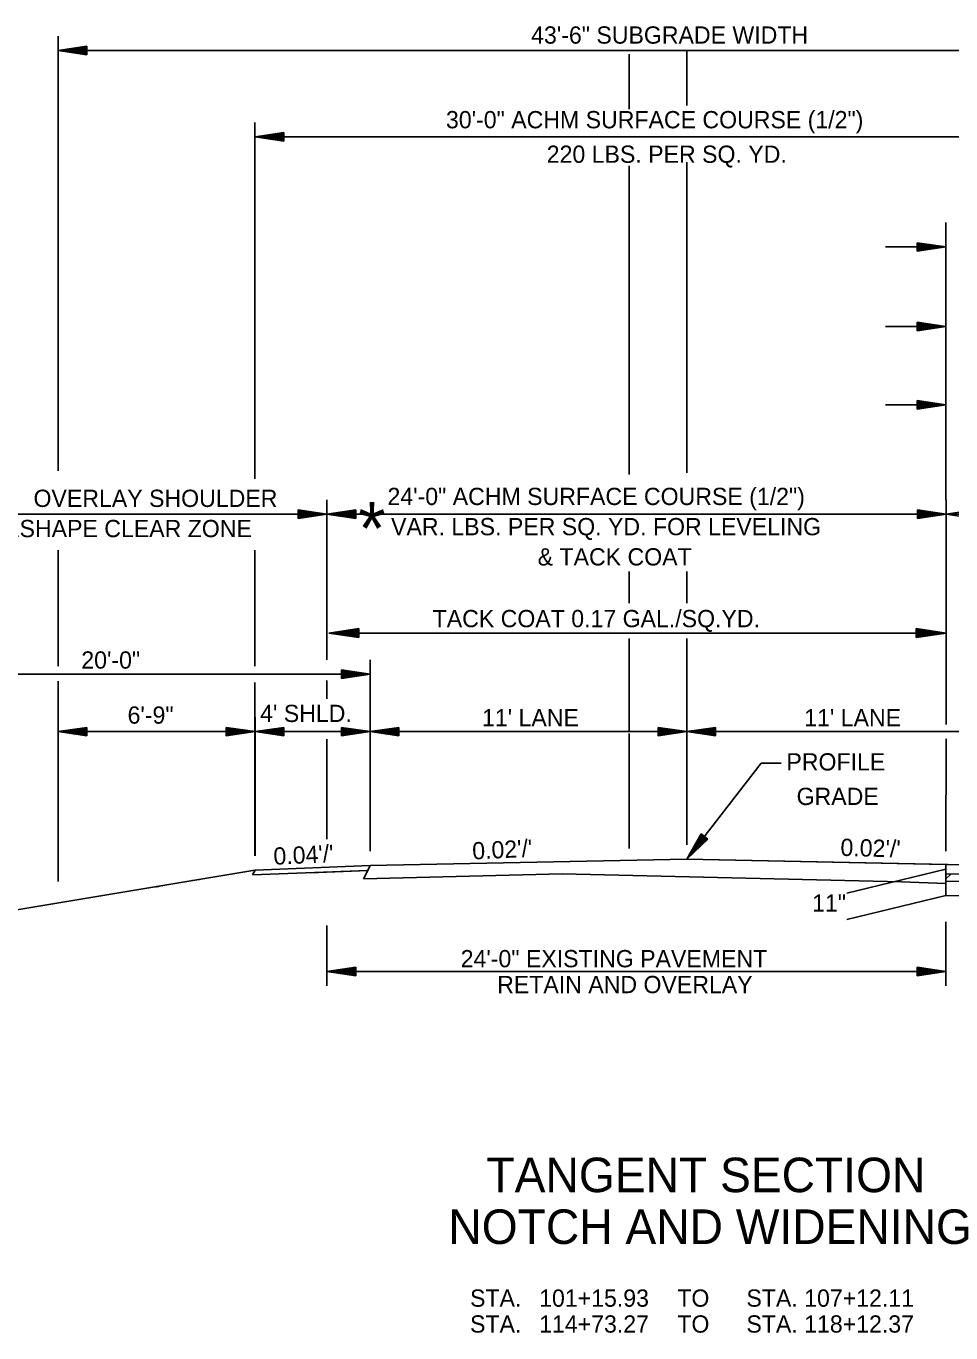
# Model space of a CAD drawing. Extents: x -900 to 15312, y 1857 to 2945.
# Drawn here: x 1911.7 to 2232.9, y 1982.2 to 2436.5 of the extents above; entities that cross this region are included whole.
import ezdxf

# ---------------------------------------------------------------- set-up
doc = ezdxf.new("R2010")
doc.units = 0
for name, color, linetype in [('Default', 7, 'Continuous'), ('R_Annotation', 7, 'Continuous'), ('R_Centerline', 7, 'Continuous'), ('R_Dimension', 7, 'Continuous')]:
    doc.layers.add(name, color=color, linetype=linetype)

msp = doc.modelspace()

# ---------------------------------------------------------------- linework, layer by layer
at = {"layer": 'Default'}
for p, q in [((2141.18, 2146.88), (2031.18, 2144.68)), ((2231.18, 2145.08), (2141.18, 2146.88)), ((2251.18, 2144.68), (2231.18, 2145.08)), ((2231.18, 2145.08), (2231.18, 2141.74)), ((2028.88, 2140.09), (2097.89, 2141.76)), ((2231.18, 2141.74), (2252.86, 2141.31)), ((2231.18, 2140.04), (2232.85, 2141.71))]:
    msp.add_line(p, q, dxfattribs=at)
for points in [[(2031.18, 2144.68), (2030.33, 2142.98), (2028.88, 2140.09)], [(2231.18, 2138.4), (2231.18, 2139.24), (2231.18, 2141.74), (2231.18, 2145.08)], [(2097.89, 2141.76), (2146.95, 2140.6), (2215.71, 2138.96), (2231.18, 2138.4)]]:
    msp.add_lwpolyline(points, dxfattribs=at)
at = {"layer": 'R_Annotation'}
for p, q in [((1991.18, 2143.08), (2031.18, 2144.68)), ((2031.18, 2144.68), (2141.18, 2146.88)), ((2251.18, 2144.68), (2141.18, 2146.88)), ((2231.18, 2145.08), (2231.18, 2134.24)), ((1991.17, 2143.08), (1831.17, 2116.41)), ((1991.18, 2143.08), (1990.33, 2141.38)), ((2010.33, 2142.18), (2030.33, 2142.98)), ((2252.86, 2141.31), (2231.18, 2141.74)), ((2254.13, 2138.78), (2231.18, 2139.24)), ((2359.6, 2131.67), (2231.18, 2134.24))]:
    msp.add_line(p, q, dxfattribs=at)
for points in [[(1971.66, 2139.82), (1971.74, 2139.83), (1971.82, 2139.82), (1971.9, 2139.82)], [(1977.02, 2140.72), (1977.02, 2140.72), (1977.02, 2140.72), (1977.02, 2140.72)], [(1977.08, 2140.72), (1977.08, 2140.72), (1977.08, 2140.72), (1977.08, 2140.73)], [(1982.92, 2141.7), (1982.87, 2141.69), (1982.82, 2141.68), (1982.77, 2141.68)], [(1984.69, 2142), (1984.69, 2142), (1984.69, 2142), (1984.7, 2142)], [(1984.7, 2142), (1984.72, 2142), (1984.74, 2142), (1984.76, 2142)], [(1957.97, 2137.54), (1957.93, 2137.53), (1957.6, 2137.42), (1957.27, 2137.34), (1956.85, 2137.31), (1956.72, 2137.31), (1956.59, 2137.31)], [(1959.1, 2137.66), (1959.12, 2137.66), (1959.14, 2137.66), (1959.16, 2137.66)], [(1969.34, 2139.42), (1969.31, 2139.42), (1969.27, 2139.42), (1969.23, 2139.42), (1969.21, 2139.42)]]:
    msp.add_open_spline(points, degree=3, dxfattribs=at)
at = {"layer": 'R_Centerline'}
for p, q in [((2121.18, 2407.57), (2121.18, 2426.69)), ((2141.18, 2408.83), (2141.18, 2427.95)), ((2121.18, 2280.6), (2121.18, 2387.88)), ((2141.18, 2281.2), (2141.18, 2389.14)), ((2121.18, 2235.82), (2121.18, 2246.84)), ((2141.18, 2235.82), (2141.18, 2246.84)), ((2121.18, 2191.65), (2121.18, 2223.59)), ((2141.18, 2151.88), (2141.18, 2223.59)), ((2121.18, 2150.62), (2121.18, 2190.61))]:
    msp.add_line(p, q, dxfattribs=at)
at = {"layer": 'R_Dimension'}
for p, q in [((1922.75, 2281.86), (1922.75, 2432.95)), ((1932.75, 2429.45), (1922.75, 2427.95)), ((1922.75, 2427.95), (2359.6, 2427.95)), ((1932.75, 2426.45), (1922.75, 2427.95)), ((1932.75, 2429.2), (1924.42, 2427.95)), ((1932.75, 2426.7), (1924.42, 2427.95)), ((1932.75, 2428.94), (1926.14, 2427.95)), ((1932.75, 2426.95), (1926.14, 2427.95)), ((1932.75, 2428.69), (1927.81, 2427.95)), ((1932.75, 2427.2), (1927.81, 2427.95)), ((1932.75, 2428.43), (1929.5, 2427.95)), ((1932.75, 2427.46), (1929.5, 2427.95)), ((1932.75, 2428.18), (1931.17, 2427.95)), ((1932.75, 2427.71), (1931.17, 2427.95)), ((1932.75, 2429.45), (1932.75, 2426.45)), ((1991.17, 2279.1), (1991.17, 2402.95)), ((2001.18, 2399.45), (1991.18, 2397.95)), ((2001.18, 2399.2), (1992.85, 2397.95)), ((2001.18, 2398.94), (1994.57, 2397.95)), ((2001.18, 2398.69), (1996.23, 2397.95)), ((2001.18, 2398.44), (1997.93, 2397.95)), ((2001.18, 2396.45), (2001.18, 2399.45)), ((2291.18, 2397.95), (1991.17, 2397.95)), ((2001.18, 2396.45), (1991.18, 2397.95)), ((2001.18, 2396.7), (1992.85, 2397.95)), ((2001.18, 2396.95), (1994.57, 2397.95)), ((2001.18, 2397.2), (1996.23, 2397.95)), ((2001.18, 2397.46), (1997.93, 2397.95)), ((2001.18, 2398.18), (1999.6, 2397.95)), ((2001.18, 2397.71), (1999.6, 2397.95)), ((2231.18, 2359.69), (2231.18, 2368.23)), ((2210.19, 2359.69), (2231.07, 2359.69)), ((2221.18, 2361.19), (2231.18, 2359.69)), ((2221.18, 2358.19), (2221.18, 2361.19)), ((2221.18, 2360.94), (2229.51, 2359.69)), ((2221.18, 2360.68), (2227.79, 2359.69)), ((2221.18, 2360.43), (2226.12, 2359.69)), ((2221.18, 2360.18), (2224.43, 2359.69)), ((2221.18, 2359.92), (2222.76, 2359.69)), ((2221.18, 2358.19), (2231.18, 2359.69)), ((2221.18, 2359.2), (2224.43, 2359.69)), ((2221.18, 2358.69), (2227.79, 2359.69)), ((2221.18, 2358.44), (2229.51, 2359.69)), ((2221.18, 2358.94), (2226.12, 2359.69)), ((2221.18, 2359.45), (2222.76, 2359.69)), ((2231.18, 2304.87), (2231.18, 2359.69)), ((2210.19, 2332.02), (2231.18, 2332.02)), ((2221.18, 2333.52), (2231.18, 2332.02)), ((2221.18, 2330.52), (2221.18, 2333.52)), ((2221.18, 2333.27), (2229.51, 2332.02)), ((2221.18, 2333.02), (2227.79, 2332.02)), ((2221.18, 2332.77), (2226.12, 2332.02)), ((2221.18, 2332.51), (2224.43, 2332.02)), ((2221.18, 2332.26), (2222.76, 2332.02)), ((2221.18, 2330.52), (2231.18, 2332.02)), ((2221.18, 2331.54), (2224.43, 2332.02)), ((2221.18, 2331.03), (2227.79, 2332.02)), ((2221.18, 2330.77), (2229.51, 2332.02)), ((2221.18, 2331.28), (2226.12, 2332.02)), ((2221.18, 2331.79), (2222.76, 2332.02)), ((2210.19, 2304.87), (2231.18, 2304.87)), ((2221.18, 2306.37), (2231.18, 2304.87)), ((2221.18, 2303.37), (2221.18, 2306.37)), ((2221.18, 2306.12), (2229.51, 2304.87)), ((2221.18, 2305.86), (2227.79, 2304.87)), ((2221.18, 2305.61), (2226.12, 2304.87)), ((2221.18, 2305.36), (2224.43, 2304.87)), ((2221.18, 2305.1), (2222.76, 2304.87)), ((2221.18, 2303.37), (2231.18, 2304.87)), ((2221.18, 2304.38), (2224.43, 2304.87)), ((2221.18, 2303.87), (2227.79, 2304.87)), ((2221.18, 2303.62), (2229.51, 2304.87)), ((2221.18, 2304.12), (2226.12, 2304.87)), ((2221.18, 2304.63), (2222.76, 2304.87)), ((2231.18, 2271.81), (2231.18, 2304.87)), ((2016.18, 2216.21), (2016.18, 2271.81)), ((2231.2, 2193.71), (2231.25, 2271.81)), ((1868.55, 2266.81), (2309.56, 2266.81)), ((2006.18, 2268.31), (2016.18, 2266.81)), ((2006.18, 2265.31), (2006.18, 2268.31)), ((2006.18, 2268.06), (2014.51, 2266.81)), ((2006.18, 2267.8), (2012.79, 2266.81)), ((2006.18, 2267.55), (2011.12, 2266.81)), ((2006.18, 2267.3), (2009.43, 2266.81)), ((2006.18, 2267.04), (2007.76, 2266.81)), ((2006.18, 2265.31), (2016.18, 2266.81)), ((2006.18, 2266.32), (2009.43, 2266.81)), ((2006.18, 2265.81), (2012.79, 2266.81)), ((2006.18, 2265.56), (2014.51, 2266.81)), ((2006.18, 2266.06), (2011.12, 2266.81)), ((2006.18, 2266.57), (2007.76, 2266.81)), ((2026.18, 2268.31), (2016.18, 2266.81)), ((2026.18, 2265.31), (2016.18, 2266.81)), ((2026.18, 2268.06), (2017.85, 2266.81)), ((2026.18, 2265.56), (2017.85, 2266.81)), ((2026.18, 2267.8), (2019.57, 2266.81)), ((2026.18, 2265.81), (2019.57, 2266.81)), ((2026.18, 2267.55), (2021.23, 2266.81)), ((2026.18, 2266.06), (2021.23, 2266.81)), ((2026.18, 2267.3), (2022.93, 2266.81)), ((2026.18, 2266.32), (2022.93, 2266.81)), ((2026.18, 2267.04), (2024.6, 2266.81)), ((2026.18, 2266.57), (2024.6, 2266.81)), ((2026.18, 2265.31), (2026.18, 2268.31)), ((2221.25, 2268.31), (2231.25, 2266.81)), ((2221.25, 2268.31), (2221.25, 2265.31)), ((2221.25, 2268.06), (2229.58, 2266.81)), ((2221.25, 2267.8), (2227.86, 2266.81)), ((2221.25, 2267.55), (2226.19, 2266.81)), ((2221.25, 2267.29), (2224.5, 2266.81)), ((2221.25, 2267.04), (2222.83, 2266.81)), ((2221.25, 2265.31), (2231.25, 2266.81)), ((2221.25, 2266.32), (2224.5, 2266.81)), ((2221.25, 2265.81), (2227.86, 2266.81)), ((2221.25, 2265.56), (2229.58, 2266.81)), ((2221.25, 2266.06), (2226.19, 2266.81)), ((2221.25, 2266.57), (2222.83, 2266.81)), ((2241.25, 2268.31), (2231.25, 2266.81)), ((2241.25, 2265.31), (2231.25, 2266.81)), ((1922.75, 2213.97), (1922.75, 2254.31)), ((1991.17, 2213.97), (1991.17, 2254.31)), ((2027.23, 2227.06), (2016.82, 2225.5)), ((2027.23, 2226.8), (2018.56, 2225.5)), ((2027.23, 2226.53), (2020.35, 2225.5)), ((2027.23, 2226.27), (2022.07, 2225.5)), ((2027.23, 2226.01), (2023.84, 2225.5)), ((2027.23, 2223.94), (2027.23, 2227.06)), ((2220.81, 2227.06), (2231.22, 2225.5)), ((2220.81, 2227.06), (2220.81, 2223.94)), ((2220.81, 2226.8), (2229.48, 2225.5)), ((2220.81, 2226.53), (2227.69, 2225.5)), ((2220.81, 2226.27), (2225.97, 2225.5)), ((2220.81, 2226), (2224.2, 2225.5)), ((2027.23, 2223.94), (2016.82, 2225.5)), ((2231.22, 2225.5), (2016.82, 2225.5)), ((2027.23, 2224.2), (2018.56, 2225.5)), ((2027.23, 2224.47), (2020.35, 2225.5)), ((2027.23, 2224.73), (2022.07, 2225.5)), ((2027.23, 2225), (2023.84, 2225.5)), ((2027.23, 2225.74), (2025.58, 2225.5)), ((2027.23, 2225.26), (2025.58, 2225.5)), ((2056.82, 2225.5), (2055.56, 2225.5)), ((2220.81, 2225.74), (2222.46, 2225.5)), ((2220.81, 2223.94), (2231.22, 2225.5)), ((2220.81, 2224.99), (2224.2, 2225.5)), ((2220.81, 2224.47), (2227.69, 2225.5)), ((2220.81, 2224.2), (2229.48, 2225.5)), ((2220.81, 2224.73), (2225.97, 2225.5)), ((2220.81, 2225.26), (2222.46, 2225.5)), ((2021.18, 2212.71), (2031.18, 2211.21)), ((2021.18, 2212.71), (2021.18, 2209.71)), ((2021.18, 2212.46), (2029.51, 2211.21)), ((2021.18, 2212.21), (2027.79, 2211.21)), ((2031.18, 2191.21), (2031.18, 2216.21)), ((1831.17, 2211.21), (2031.18, 2211.21)), ((1922.75, 2139.14), (1922.75, 2208.71)), ((1991.17, 2148.08), (1991.17, 2208.33)), ((2016.18, 2202.67), (2016.18, 2209.01)), ((2021.18, 2211.96), (2026.12, 2211.21)), ((2021.18, 2211.7), (2024.43, 2211.21)), ((2021.18, 2211.45), (2022.76, 2211.21)), ((2021.18, 2209.71), (2031.18, 2211.21)), ((2021.18, 2210.72), (2024.43, 2211.21)), ((2021.18, 2210.22), (2027.79, 2211.21)), ((2021.18, 2209.96), (2029.51, 2211.21)), ((2021.18, 2210.47), (2026.12, 2211.21)), ((2021.18, 2210.98), (2022.76, 2211.21)), ((1991.18, 2148.08), (1991.18, 2196.21)), ((1932.75, 2192.71), (1922.75, 2191.21)), ((2359.6, 2191.21), (1922.75, 2191.21)), ((1932.75, 2189.71), (1922.75, 2191.21)), ((1932.75, 2192.46), (1924.42, 2191.21)), ((1932.75, 2189.96), (1924.42, 2191.21)), ((1932.75, 2192.21), (1926.14, 2191.21)), ((1932.75, 2190.22), (1926.14, 2191.21)), ((1932.75, 2191.96), (1927.81, 2191.21)), ((1932.75, 2190.47), (1927.81, 2191.21)), ((1932.75, 2191.7), (1929.5, 2191.21)), ((1932.75, 2190.72), (1929.5, 2191.21)), ((1932.75, 2191.45), (1931.17, 2191.21)), ((1932.75, 2190.98), (1931.17, 2191.21)), ((1932.75, 2192.71), (1932.75, 2189.71)), ((1981.18, 2192.71), (1991.18, 2191.21)), ((1981.18, 2192.71), (1981.18, 2189.71)), ((1981.18, 2192.46), (1989.51, 2191.21)), ((1981.18, 2192.21), (1987.79, 2191.21)), ((1981.18, 2191.96), (1986.12, 2191.21)), ((1981.18, 2191.7), (1984.43, 2191.21)), ((1981.18, 2191.45), (1982.76, 2191.21)), ((1981.18, 2189.71), (1991.18, 2191.21)), ((1981.18, 2190.72), (1984.43, 2191.21)), ((1981.18, 2190.22), (1987.79, 2191.21)), ((1981.18, 2189.96), (1989.51, 2191.21)), ((1981.18, 2190.47), (1986.12, 2191.21)), ((1981.18, 2190.98), (1982.76, 2191.21)), ((2001.18, 2192.71), (1991.18, 2191.21)), ((2001.18, 2189.71), (1991.18, 2191.21)), ((2001.18, 2192.46), (1992.85, 2191.21)), ((2001.18, 2189.96), (1992.85, 2191.21)), ((2001.18, 2192.21), (1994.57, 2191.21)), ((2001.18, 2190.22), (1994.57, 2191.21)), ((2001.18, 2191.96), (1996.23, 2191.21)), ((2001.18, 2190.47), (1996.23, 2191.21)), ((2001.18, 2191.7), (1997.93, 2191.21)), ((2001.18, 2190.73), (1997.93, 2191.21)), ((2001.18, 2191.45), (1999.6, 2191.21)), ((2001.18, 2190.98), (1999.6, 2191.21)), ((2001.18, 2189.71), (2001.18, 2192.71)), ((2021.18, 2192.71), (2031.18, 2191.21)), ((2021.18, 2192.71), (2021.18, 2189.71)), ((2021.18, 2192.46), (2029.51, 2191.21)), ((2021.18, 2192.21), (2027.79, 2191.21)), ((2021.18, 2191.96), (2026.12, 2191.21)), ((2021.18, 2191.7), (2024.43, 2191.21)), ((2021.18, 2191.45), (2022.76, 2191.21)), ((2021.18, 2189.71), (2031.18, 2191.21)), ((2021.18, 2190.72), (2024.43, 2191.21)), ((2021.18, 2190.22), (2027.79, 2191.21)), ((2021.18, 2189.96), (2029.51, 2191.21)), ((2021.18, 2190.47), (2026.12, 2191.21)), ((2021.18, 2190.98), (2022.76, 2191.21)), ((2041.18, 2192.71), (2031.18, 2191.21)), ((2031.18, 2149.68), (2031.18, 2191.21)), ((2041.18, 2189.71), (2031.18, 2191.21)), ((2041.18, 2192.46), (2032.85, 2191.21)), ((2041.18, 2189.96), (2032.85, 2191.21)), ((2041.18, 2192.21), (2034.57, 2191.21)), ((2041.18, 2190.22), (2034.57, 2191.21)), ((2041.18, 2191.96), (2036.23, 2191.21)), ((2041.18, 2190.47), (2036.23, 2191.21)), ((2041.18, 2191.7), (2037.93, 2191.21)), ((2041.18, 2190.73), (2037.93, 2191.21)), ((2041.18, 2191.45), (2039.6, 2191.21)), ((2041.18, 2190.98), (2039.6, 2191.21)), ((2041.18, 2189.71), (2041.18, 2192.71)), ((2131.18, 2192.71), (2141.18, 2191.21)), ((2131.18, 2192.71), (2131.18, 2189.71)), ((2131.18, 2192.46), (2139.51, 2191.21)), ((2131.18, 2192.21), (2137.79, 2191.21)), ((2131.18, 2191.96), (2136.12, 2191.21)), ((2131.18, 2191.7), (2134.43, 2191.21)), ((2131.18, 2191.45), (2132.76, 2191.21)), ((2131.18, 2189.71), (2141.18, 2191.21)), ((2131.18, 2190.72), (2134.43, 2191.21)), ((2131.18, 2190.22), (2137.79, 2191.21)), ((2131.18, 2189.96), (2139.51, 2191.21)), ((2131.18, 2190.47), (2136.12, 2191.21)), ((2131.18, 2190.98), (2132.76, 2191.21)), ((2151.18, 2192.71), (2141.18, 2191.21)), ((2151.18, 2189.71), (2141.18, 2191.21)), ((2151.18, 2192.46), (2142.85, 2191.21)), ((2151.18, 2189.96), (2142.85, 2191.21)), ((2151.18, 2192.21), (2144.57, 2191.21)), ((2151.18, 2190.22), (2144.57, 2191.21)), ((2151.18, 2191.96), (2146.23, 2191.21)), ((2151.18, 2190.47), (2146.23, 2191.21)), ((2151.18, 2191.7), (2147.93, 2191.21)), ((2151.18, 2190.73), (2147.93, 2191.21)), ((2151.18, 2191.45), (2149.6, 2191.21)), ((2151.18, 2190.98), (2149.6, 2191.21)), ((2151.18, 2189.71), (2151.18, 2192.71)), ((2016.18, 2153.78), (2016.18, 2188.59)), ((2231.18, 2149.68), (2231.2, 2188.71)), ((2146.12, 2155.7), (2141.18, 2146.88)), ((2148.49, 2153.86), (2141.18, 2146.88)), ((2146.32, 2155.55), (2142.2, 2148.2)), ((2148.3, 2154.01), (2142.2, 2148.2)), ((2146.52, 2155.39), (2143.26, 2149.56)), ((2148.09, 2154.17), (2143.26, 2149.56)), ((2146.72, 2155.24), (2144.28, 2150.87)), ((2147.9, 2154.32), (2144.28, 2150.87)), ((2146.92, 2155.08), (2145.32, 2152.21)), ((2147.69, 2154.48), (2145.32, 2152.21)), ((2148.49, 2153.86), (2146.12, 2155.7)), ((2147.12, 2154.92), (2146.34, 2153.53)), ((2147.49, 2154.64), (2146.34, 2153.53)), ((2031.18, 2144.68), (1991.18, 2143.08)), ((2030.33, 2142.98), (2031.18, 2144.68)), ((1991.18, 2143.08), (1990.33, 2141.38)), ((1990.33, 2141.38), (2030.33, 2142.98)), ((2231.18, 2143.41), (2196.73, 2135.05)), ((2231.18, 2134.24), (2196.73, 2125.89)), ((2016.18, 2102.85), (2016.18, 2123.83)), ((2231.18, 2102.85), (2231.18, 2125.07)), ((2026.18, 2109.35), (2016.18, 2107.85)), ((2026.18, 2106.35), (2016.18, 2107.85)), ((2231.18, 2107.85), (2016.18, 2107.85)), ((2026.18, 2109.1), (2017.85, 2107.85)), ((2026.18, 2106.6), (2017.85, 2107.85)), ((2026.18, 2108.85), (2019.57, 2107.85)), ((2026.18, 2106.86), (2019.57, 2107.85)), ((2026.18, 2108.6), (2021.23, 2107.85)), ((2026.18, 2107.11), (2021.23, 2107.85)), ((2026.18, 2108.34), (2022.93, 2107.85)), ((2026.18, 2107.37), (2022.93, 2107.85)), ((2026.18, 2108.09), (2024.6, 2107.85)), ((2026.18, 2107.62), (2024.6, 2107.85)), ((2026.18, 2106.35), (2026.18, 2109.35)), ((2221.18, 2109.35), (2231.18, 2107.85)), ((2221.18, 2109.35), (2221.18, 2106.35)), ((2221.18, 2109.1), (2229.51, 2107.85)), ((2221.18, 2108.85), (2227.79, 2107.85)), ((2221.18, 2108.6), (2226.12, 2107.85)), ((2221.18, 2108.34), (2224.43, 2107.85)), ((2221.18, 2108.09), (2222.76, 2107.85)), ((2221.18, 2106.35), (2231.18, 2107.85)), ((2221.18, 2107.36), (2224.43, 2107.85)), ((2221.18, 2106.86), (2227.79, 2107.85)), ((2221.18, 2106.6), (2229.51, 2107.85)), ((2221.18, 2107.11), (2226.12, 2107.85)), ((2221.18, 2107.62), (2222.76, 2107.85))]:
    msp.add_line(p, q, dxfattribs=at)
msp.add_lwpolyline([(2141.18, 2146.88), (2167.03, 2180.2), (2173.89, 2180.2)], dxfattribs=at)

# ---------------------------------------------------------------- texts
at = {"layer": 'R_Annotation'}
for s, height, p in [('43\'-6" SUBGRADE WIDTH', 6, (2087.09, 2430.38)), ('30\'-0" ACHM SURFACE COURSE (1/2")', 6, (2057.51, 2400.95)), ('220 LBS. PER SQ. YD.', 6, (2092.51, 2388.95)), ('24\'-0" ACHM SURFACE COURSE (1/2")', 6, (2037.19, 2269.98)), ('OVERLAY SHOULDER', 6, (1914.24, 2269.32)), ('*', 18.39, (2027, 2252.69)), ('& RESHAPE CLEAR ZONE', 6, (1890.66, 2258.82)), ('VAR. LBS. PER SQ. YD. FOR LEVELING', 6, (2038.44, 2259.48)), ('& TACK COAT', 6, (2089.37, 2248.98)), ('TACK COAT 0.17 GAL./SQ.YD.', 6, (2052.88, 2227.52)), ('20\'-0"', 6, (1930.84, 2213.12)), ('6\'-9"', 6, (1946.91, 2193.98)), ("4' SHLD.", 6, (1992.95, 2194.56)), ("11' LANE", 6, (2070.03, 2193.05)), ("11' LANE", 6, (2181.95, 2193.05)), ('PROFILE', 6, (2175.76, 2177.71)), ('GRADE', 6, (2179.3, 2165.71)), ('11"', 6, (2184.69, 2128.63)), ('24\'-0" EXISTING PAVEMENT', 6, (2062.62, 2109.3)), ('RETAIN AND OVERLAY', 6, (2075.3, 2100.3)), ('TANGENT SECTION', 12, (2071.57, 2031.12)), ('NOTCH AND WIDENING', 12, (2058.34, 2013.12)), ('STA. ', 6, (2065.87, 1991.3)), ('101+15.93 ', 6, (2089.87, 1991.3)), ('TO ', 6, (2137.87, 1991.3)), ('STA. 107+12.11', 6, (2161.87, 1991.3)), ('STA. ', 6, (2065.87, 1982.3)), ('114+73.27 ', 6, (2089.87, 1982.3)), ('TO ', 6, (2137.87, 1982.3)), ('STA. 118+12.37', 6, (2161.87, 1982.3))]:
    msp.add_text(s, height=height, dxfattribs=at).set_placement(p)
for s, rotation, p in [("0.02'/'", 2.7804, (2066.78, 2146.74)), ("0.02'/'", 358.3978, (2194.47, 2148.05)), ("0.04'/'", 2.7804, (1997.72, 2144.9))]:
    msp.add_text(s, height=6, rotation=rotation, dxfattribs=at).set_placement(p)

doc.saveas('drawing.dxf')
